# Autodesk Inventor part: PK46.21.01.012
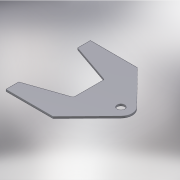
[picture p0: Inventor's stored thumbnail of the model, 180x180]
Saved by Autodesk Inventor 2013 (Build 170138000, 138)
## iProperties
Created: 2005-04
Part Number: PK46.21.01.012
Material: Steel, Mild
Document SubType Name: Modeling
Designer: salex
Manufacturer: Standard
Standards Organization: Custom
Density: 7.86 g/cm^3
Author: salex
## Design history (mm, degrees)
sketch "Эскиз1"
  geometry: L1 (0, 0)-(-241.647, 0); L2 (82.167, 80.458)-(-265, 435); L3 (-265, 435)-(-750, 435); L4 (-750, 435)-(-750, 305); L5 (-750, 305)-(-330, 160); L6 (-330, 160)-(-330, -160); L7 (82.167, -80.458)-(-265, -435); L8 (-265, -435)-(-750, -435); L9 (-750, -305)-(-330, -160); L10 (-750, -435)-(-750, -305); C1 r 40 at (0, 0); A1 r 115 centre (0, 0) between (82.167, -80.458) and (82.167, 80.458)
  constraints: 20 end point, 4 symmetric about line, 2 centre point, 2 point on circle, 1 coincident, 1 equal length, 1 horizontal, 1 parallel, 1 perpendicular, 1 tangent, 1 other
  dimensions: "d0" = 115 radius of A1; "d1" = 80 diameter of C1; "d2" = 750 distance from line of L4 C1.centre; "d3" = 870 diameter of L3 L1; "d4" = 130 distance of L3.end L4.end; "d5" = 330 distance from line of C1.centre L6; "d9" = 265 horizontal distance of L2.end L1.start; "d17" = 275 distance from line of L6.end L8; "d18" = 275 distance from line of L5.end L3 (= d17)
extrude "Выдавливание1" new body sketch "Эскиз1" distance "d11" = 20; taper "d12" = 0 deg
fillet "Сопряжение2" dims "d19" = 20
body "Solid1"
